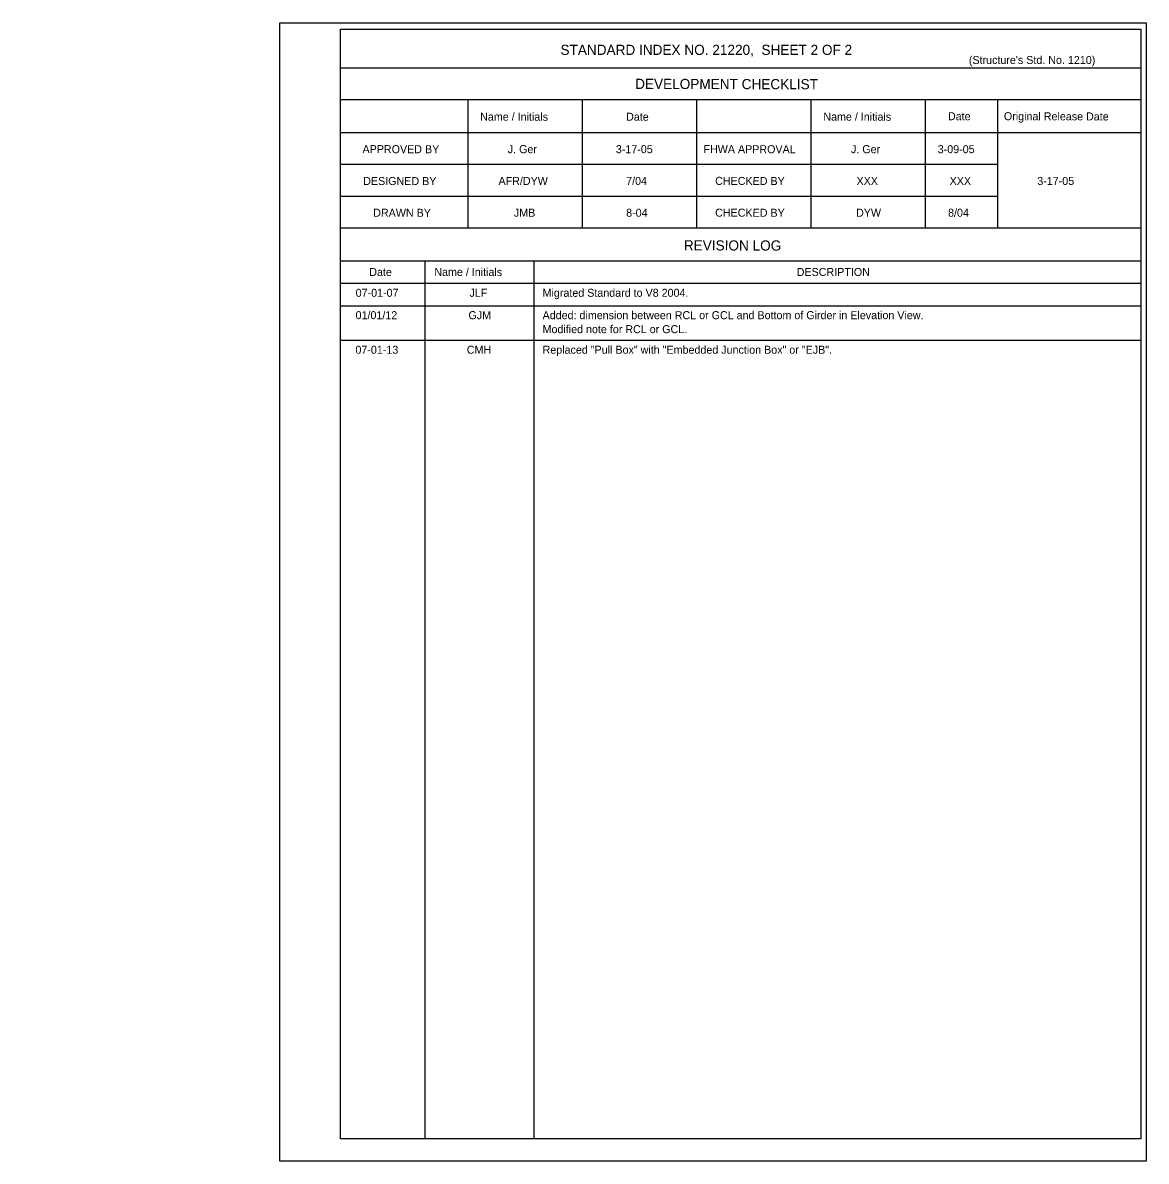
# Model space of a CAD drawing. Extents: x 83976.6 to 84012, y 72958.9 to 72975.6.
# Drawn here: x 83997.84 to 84011.99, y 72958.9 to 72973.23 of the extents above; entities that cross this region are included whole.
import ezdxf

# ---------------------------------------------------------------- set-up
doc = ezdxf.new("R2010")
doc.units = 0
for name, color, linetype in [('DSDate', 7, 'Continuous'), ('Patterning', 7, 'Continuous'), ('SheetBorder_dp', 7, 'Continuous'), ('SheetLines_dp', 7, 'Continuous')]:
    doc.layers.add(name, color=color, linetype=linetype)

msp = doc.modelspace()

# ---------------------------------------------------------------- linework, layer by layer
at = {"layer": 'DSDate'}
for p, q in [((84011.919, 72972.659), (84001.845, 72972.659)), ((84011.919, 72972.259), (84001.845, 72972.259)), ((84003.445, 72972.259), (84003.445, 72970.645)), ((84004.885, 72972.259), (84004.885, 72970.645)), ((84006.325, 72972.259), (84006.325, 72970.645)), ((84007.765, 72972.259), (84007.765, 72970.645)), ((84009.205, 72972.259), (84009.205, 72970.645)), ((84010.113, 72972.259), (84010.113, 72970.645)), ((84011.919, 72971.845), (84001.845, 72971.845)), ((84010.113, 72971.445), (84001.845, 72971.445)), ((84010.113, 72971.045), (84001.845, 72971.045)), ((84011.919, 72970.645), (84001.845, 72970.645)), ((84011.919, 72970.231), (84001.845, 72970.231)), ((84002.905, 72970.231), (84002.905, 72959.178)), ((84004.277, 72970.231), (84004.277, 72959.178)), ((84011.919, 72969.95), (84001.845, 72969.95))]:
    msp.add_line(p, q, dxfattribs=at)
msp.add_lwpolyline([(84001.845, 72973.15), (84011.919, 72973.15), (84011.919, 72959.178), (84001.845, 72959.178)], close=True, dxfattribs=at)
at = {"layer": 'SheetBorder_dp'}
for p, q in [((83997.845, 72973.231), (83997.845, 72973.231)), ((84001.08, 72958.898), (84001.08, 72958.898))]:
    msp.add_line(p, q, dxfattribs=at)
msp.add_lwpolyline([(84001.08, 72973.231), (84011.987, 72973.231), (84011.987, 72958.898), (84001.08, 72958.898)], close=True, dxfattribs=at)
at = {"layer": 'SheetLines_dp'}
for p, q in [((84001.845, 72969.668), (84011.919, 72969.668)), ((84001.845, 72969.233), (84011.919, 72969.233))]:
    msp.add_line(p, q, dxfattribs=at)

# ---------------------------------------------------------------- texts
at = {"layer": 'Patterning'}
for s, height, p in [('STANDARD INDEX NO. 21220,  SHEET 2 OF 2', 0.128, (84004.613, 72972.826)), ("(Structure's Std. No. 1210)", 0.1008, (84009.754, 72972.712)), ('J. Ger', 0.1008, (84003.95, 72971.589)), ('3-17-05', 0.1008, (84005.31, 72971.589)), ('J. Ger', 0.1008, (84008.27, 72971.589)), ('3-09-05', 0.1008, (84009.362, 72971.589)), ('AFR/DYW', 0.1008, (84003.833, 72971.189)), ('7/04', 0.1008, (84005.44, 72971.189)), ('XXX', 0.1008, (84008.34, 72971.189)), ('XXX', 0.1008, (84009.512, 72971.189)), ('3-17-05', 0.1008, (84010.615, 72971.189)), ('JMB', 0.1008, (84004.027, 72970.789)), ('8-04', 0.1008, (84005.44, 72970.789)), ('DYW', 0.1008, (84008.334, 72970.789)), ('8/04', 0.1008, (84009.492, 72970.789)), ('DESCRIPTION', 0.1008, (84007.587, 72970.043)), ('07-01-07', 0.1008, (84002.035, 72969.781)), ('JLF', 0.1008, (84003.468, 72969.781)), ('Migrated Standard to V8 2004.', 0.1008, (84004.388, 72969.781)), ('01/01/12', 0.1008, (84002.034, 72969.499)), ('GJM', 0.1008, (84003.455, 72969.499)), ('Added: dimension between RCL or GCL and Bottom of Girder in Elevation View.', 0.1008, (84004.388, 72969.499)), ('Modified note for RCL or GCL.', 0.1008, (84004.388, 72969.323)), ('07-01-13', 0.1008, (84002.032, 72969.064)), ('CMH', 0.1008, (84003.434, 72969.064)), ('Replaced "Pull Box" with "Embedded Junction Box" or "EJB".', 0.1008, (84004.388, 72969.064))]:
    msp.add_text(s, height=height, dxfattribs=at).set_placement(p)
for s, height, p in [('DEVELOPMENT CHECKLIST', 0.128, (84005.553, 72972.398)), ('Name / Initials', 0.1008, (84003.602, 72971.999)), ('Date', 0.1008, (84005.439, 72971.998)), ('Name / Initials', 0.1008, (84007.922, 72971.999)), ('Date', 0.1008, (84009.491, 72972.004)), ('Original Release Date', 0.1008, (84010.195, 72972.004)), ('APPROVED BY', 0.1008, (84002.121, 72971.59)), ('FHWA APPROVAL', 0.1008, (84006.413, 72971.59)), ('DESIGNED BY', 0.1008, (84002.13, 72971.189)), ('CHECKED BY', 0.1008, (84006.56, 72971.19)), ('DRAWN BY', 0.1008, (84002.256, 72970.789)), ('CHECKED BY', 0.1008, (84006.56, 72970.79)), ('REVISION LOG', 0.128, (84006.166, 72970.365)), ('Date', 0.1008, (84002.206, 72970.043)), ('Name / Initials', 0.1008, (84003.025, 72970.044))]:
    msp.add_text(s, height=height, rotation=359.8756, dxfattribs=at).set_placement(p)

doc.saveas('drawing.dxf')
